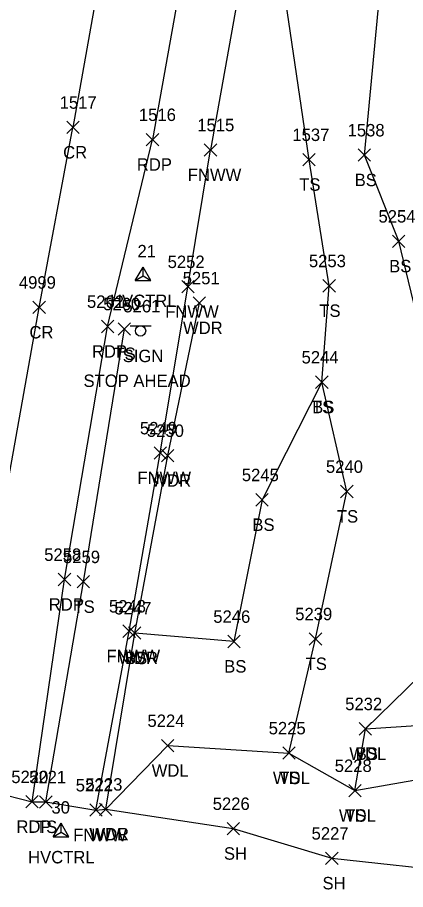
# Model space of a CAD drawing. Extents: x 1509053 to 1511576, y 400838 to 402572.
# Drawn here: x 1509729.1 to 1509791.5, y 401145.8 to 401286.1 of the extents above; entities that cross this region are included whole.
import ezdxf

# ---------------------------------------------------------------- set-up
doc = ezdxf.new("R2010")
doc.units = 0
for name, color, linetype in [('C_A', 7, 'Continuous'), ('C_I', 7, 'Continuous'), ('CPSM', 7, 'Continuous'), ('L_A', 7, 'Continuous'), ('L_I', 7, 'Continuous'), ('L_TIC', 7, 'Continuous'), ('LAWA', 7, 'Continuous'), ('LELB', 7, 'Continuous'), ('LFNC', 7, 'Continuous'), ('LSOGP', 7, 'Continuous'), ('P_A', 7, 'Continuous'), ('P_I', 7, 'Continuous'), ('P_TIC', 7, 'Continuous'), ('PET', 7, 'Continuous'), ('PRC', 7, 'Continuous'), ('S_A', 7, 'Continuous'), ('S_C', 7, 'Continuous'), ('S_I', 7, 'Continuous'), ('SSGN', 7, 'Continuous')]:
    doc.layers.add(name, color=color, linetype=linetype)

msp = doc.modelspace()

# ---------------------------------------------------------------- linework, layer by layer
at = {"layer": 'CPSM'}
for p, q in [((1509748.06, 401243.81), (1509749.31, 401245.97)), ((1509750.56, 401243.81), (1509749.31, 401245.97)), ((1509749.32, 401244.53), (1509749.31, 401245.97)), ((1509748.06, 401243.81), (1509749.32, 401244.53)), ((1509748.06, 401243.81), (1509750.56, 401243.81)), ((1509749.32, 401244.53), (1509749.32, 401244.53)), ((1509749.32, 401244.53), (1509750.56, 401243.81)), ((1509734.89, 401154.34), (1509736.14, 401156.51)), ((1509737.39, 401154.34), (1509736.14, 401156.51)), ((1509736.14, 401155.06), (1509736.14, 401156.51)), ((1509734.89, 401154.34), (1509736.14, 401155.06)), ((1509734.89, 401154.34), (1509737.39, 401154.34)), ((1509736.14, 401155.06), (1509736.14, 401155.06)), ((1509736.14, 401155.06), (1509737.39, 401154.34))]:
    msp.add_line(p, q, dxfattribs=at)
at = {"layer": 'L_TIC'}
for points in [[(1509759.17, 401263.81), (1509761.17, 401265.81)], [(1509761.17, 401263.81), (1509759.17, 401265.81)], [(1509783.91, 401262.98), (1509785.9, 401264.98)], [(1509785.9, 401262.98), (1509783.91, 401264.98)], [(1509775.02, 401262.24), (1509777.02, 401264.24)], [(1509777.02, 401262.24), (1509775.02, 401264.24)], [(1509789.44, 401249.12), (1509791.44, 401251.12)], [(1509791.44, 401249.12), (1509789.44, 401251.12)], [(1509755.53, 401241.81), (1509757.53, 401243.81)], [(1509757.53, 401241.81), (1509755.53, 401243.81)], [(1509778.25, 401241.95), (1509780.25, 401243.95)], [(1509780.25, 401241.95), (1509778.25, 401243.95)], [(1509757.38, 401239.19), (1509759.38, 401241.19)], [(1509759.38, 401239.19), (1509757.38, 401241.19)], [(1509745.31, 401235.02), (1509747.31, 401237.02)], [(1509747.31, 401235.02), (1509745.31, 401237.02)], [(1509777.07, 401226.46), (1509779.07, 401228.46)], [(1509779.07, 401226.46), (1509777.07, 401228.46)], [(1509777.07, 401226.46), (1509779.07, 401228.46)], [(1509779.07, 401226.46), (1509777.07, 401228.46)], [(1509751.08, 401215.06), (1509753.08, 401217.06)], [(1509753.08, 401215.06), (1509751.08, 401217.06)], [(1509752.29, 401214.65), (1509754.29, 401216.65)], [(1509754.29, 401214.65), (1509752.29, 401216.65)], [(1509781.08, 401208.87), (1509783.08, 401210.87)], [(1509783.08, 401208.87), (1509781.08, 401210.87)], [(1509767.46, 401207.53), (1509769.46, 401209.53)], [(1509769.46, 401207.53), (1509767.46, 401209.53)], [(1509738.72, 401194.35), (1509740.72, 401196.35)], [(1509740.72, 401194.35), (1509738.72, 401196.35)], [(1509746.09, 401186.41), (1509748.09, 401188.41)], [(1509748.09, 401186.41), (1509746.09, 401188.41)], [(1509746.97, 401186.1), (1509748.97, 401188.1)], [(1509748.97, 401186.1), (1509746.97, 401188.1)], [(1509746.97, 401186.1), (1509748.97, 401188.1)], [(1509748.97, 401186.1), (1509746.97, 401188.1)], [(1509762.93, 401184.75), (1509764.93, 401186.75)], [(1509764.93, 401184.75), (1509762.93, 401186.75)], [(1509776.05, 401185.16), (1509778.05, 401187.16)], [(1509778.05, 401185.16), (1509776.05, 401187.16)], [(1509784.08, 401170.7), (1509786.08, 401172.7)], [(1509786.08, 401170.7), (1509784.08, 401172.7)], [(1509784.08, 401170.7), (1509786.08, 401172.7)], [(1509786.08, 401170.7), (1509784.08, 401172.7)], [(1509752.29, 401168), (1509754.29, 401170)], [(1509754.29, 401168), (1509752.29, 401170)], [(1509771.78, 401166.81), (1509773.78, 401168.81)], [(1509773.78, 401166.81), (1509771.78, 401168.81)], [(1509771.78, 401166.81), (1509773.78, 401168.81)], [(1509773.78, 401166.81), (1509771.78, 401168.81)], [(1509782.4, 401160.76), (1509784.4, 401162.76)], [(1509784.4, 401160.76), (1509782.4, 401162.76)], [(1509782.4, 401160.76), (1509784.4, 401162.76)], [(1509784.4, 401160.76), (1509782.4, 401162.76)], [(1509732.69, 401158.94), (1509734.69, 401160.94)], [(1509734.69, 401158.94), (1509732.69, 401160.94)], [(1509740.75, 401157.63), (1509742.75, 401159.63)], [(1509742.75, 401157.63), (1509740.75, 401159.63)], [(1509742.31, 401157.76), (1509744.31, 401159.76)], [(1509744.31, 401157.76), (1509742.31, 401159.76)], [(1509742.31, 401157.76), (1509744.31, 401159.76)], [(1509744.31, 401157.76), (1509742.31, 401159.76)], [(1509762.83, 401154.65), (1509764.83, 401156.65)], [(1509764.83, 401154.65), (1509762.83, 401156.65)], [(1509778.68, 401149.88), (1509780.68, 401151.88)], [(1509780.68, 401149.88), (1509778.68, 401151.88)]]:
    msp.add_lwpolyline(points, dxfattribs=at)
at = {"layer": 'LAWA'}
for points in [[(1509743.31, 401158.76), (1509753.29, 401169), (1509772.78, 401167.81), (1509783.4, 401161.76), (1509785.08, 401171.7), (1509800.61, 401172.7), (1509812.47, 401171.07), (1509811.72, 401192.32), (1509812.58, 401209.09), (1509807.76, 401230.97), (1509813.05, 401256.02)], [(1509743.31, 401158.76), (1509747.97, 401187.1), (1509753.29, 401215.65), (1509758.38, 401240.19)]]:
    msp.add_lwpolyline(points, dxfattribs=at)
at = {"layer": 'LELB'}
for points in [[(1509784.91, 401263.98), (1509794.11, 401361.03)], [(1509776.02, 401263.24), (1509768.73, 401312.75)], [(1509779.25, 401242.95), (1509776.02, 401263.24)], [(1509790.44, 401250.12), (1509784.91, 401263.98)], [(1509785.08, 401171.7), (1509796.05, 401182.39), (1509797.2, 401198.58), (1509795.66, 401206.85), (1509794.77, 401232.19), (1509790.44, 401250.12)], [(1509772.78, 401167.81), (1509777.05, 401186.16), (1509782.08, 401209.87), (1509778.07, 401227.46), (1509779.25, 401242.95)], [(1509733.69, 401159.94), (1509739.72, 401195.35), (1509746.31, 401236.02)], [(1509778.07, 401227.46), (1509768.46, 401208.53), (1509763.93, 401185.75), (1509747.97, 401187.1)], [(1509783.4, 401161.76), (1509800.18, 401164.72), (1509810.11, 401160.61)]]:
    msp.add_lwpolyline(points, dxfattribs=at)
at = {"layer": 'LFNC'}
for points in [[(1509788.09, 401418.27), (1509778.14, 401361.9), (1509768.73, 401312.75), (1509760.17, 401264.81)], [(1509756.53, 401242.81), (1509760.17, 401264.81)], [(1509741.75, 401158.63), (1509747.09, 401187.41), (1509752.08, 401216.06), (1509756.53, 401242.81)]]:
    msp.add_lwpolyline(points, dxfattribs=at)
at = {"layer": 'LSOGP'}
msp.add_lwpolyline([(1509718.9, 401163.18), (1509731.47, 401159.97), (1509733.69, 401159.94), (1509741.75, 401158.63), (1509743.31, 401158.76), (1509763.83, 401155.65), (1509779.68, 401150.88), (1509801.41, 401148.54)], dxfattribs=at)
at = {"layer": 'P_TIC'}
for points in [[(1509737.04, 401267.43), (1509739.04, 401269.43)], [(1509739.04, 401267.43), (1509737.04, 401269.43)], [(1509749.83, 401265.46), (1509751.83, 401267.46)], [(1509751.83, 401265.46), (1509749.83, 401267.46)], [(1509731.62, 401238.49), (1509733.62, 401240.49)], [(1509733.62, 401238.49), (1509731.62, 401240.49)], [(1509742.61, 401235.4), (1509744.61, 401237.4)], [(1509744.61, 401235.4), (1509742.61, 401237.4)], [(1509735.68, 401194.71), (1509737.68, 401196.71)], [(1509737.68, 401194.71), (1509735.68, 401196.71)], [(1509730.47, 401158.97), (1509732.47, 401160.97)], [(1509732.47, 401158.97), (1509730.47, 401160.97)]]:
    msp.add_lwpolyline(points, dxfattribs=at)
at = {"layer": 'PET'}
for points in [[(1509812.34, 401557.62), (1509800.22, 401536.88), (1509792.46, 401505.8), (1509783.79, 401462.54), (1509775.66, 401414.3), (1509767.41, 401364.72), (1509759.54, 401315.03), (1509750.83, 401266.46)], [(1509743.61, 401236.4), (1509750.83, 401266.46)], [(1509731.47, 401159.97), (1509736.68, 401195.71), (1509743.61, 401236.4)]]:
    msp.add_lwpolyline(points, dxfattribs=at)
at = {"layer": 'PRC'}
for points in [[(1509754.64, 401366.79), (1509746.79, 401317.6), (1509738.04, 401268.43)], [(1509732.62, 401239.49), (1509738.04, 401268.43)], [(1509718.9, 401163.18), (1509725.18, 401197.96), (1509732.62, 401239.49)]]:
    msp.add_lwpolyline(points, dxfattribs=at)
at = {"layer": 'SSGN'}
for p, q in [((1509747.27, 401236.53), (1509750.6, 401236.53)), ((1509748.91, 401235.7), (1509748.91, 401235.7))]:
    msp.add_line(p, q, dxfattribs=at)
msp.add_circle((1509748.91, 401235.7), 0.833, dxfattribs=at)

# ---------------------------------------------------------------- texts
at = {"layer": 'C_A'}
for p in [(1509744.01, 401239.53), (1509730.83, 401150.06)]:
    msp.add_text('HVCTRL', height=2, dxfattribs=at).set_placement(p)
at = {"layer": 'C_I'}
for s, p in [('21', (1509748.42, 401247.53)), ('30', (1509734.59, 401158.06))]:
    msp.add_text(s, height=2, dxfattribs=at).set_placement(p)
at = {"layer": 'L_A'}
for s, p in [('FNWW', (1509756.51, 401259.81)), ('BS', (1509783.35, 401258.98)), ('TS', (1509774.43, 401258.24)), ('BS', (1509788.89, 401245.12)), ('FNWW', (1509752.88, 401237.81)), ('TS', (1509777.66, 401237.95)), ('WDR', (1509755.74, 401235.19)), ('TS', (1509744.72, 401231.02)), ('TS', (1509776.48, 401222.46)), ('BS', (1509776.51, 401222.46)), ('FNWW', (1509748.42, 401211.06)), ('WDR', (1509750.65, 401210.65)), ('TS', (1509780.49, 401204.87)), ('BS', (1509766.9, 401203.53)), ('TS', (1509738.13, 401190.35)), ('FNWW', (1509743.44, 401182.41)), ('WDR', (1509745.33, 401182.1)), ('BS', (1509746.41, 401182.1)), ('BS', (1509762.37, 401180.75)), ('TS', (1509775.46, 401181.16)), ('WDL', (1509782.5, 401166.7)), ('BS', (1509783.52, 401166.7)), ('WDL', (1509750.71, 401164)), ('WDL', (1509770.2, 401162.81)), ('TS', (1509771.19, 401162.81)), ('WDL', (1509780.82, 401156.76)), ('TS', (1509781.81, 401156.76)), ('TS', (1509732.1, 401154.94)), ('FNWW', (1509738.09, 401153.63)), ('WDR', (1509740.67, 401153.76)), ('WDL', (1509740.72, 401153.76)), ('SH', (1509762.32, 401150.65)), ('SH', (1509778.17, 401145.88))]:
    msp.add_text(s, height=2, dxfattribs=at).set_placement(p)
at = {"layer": 'L_I'}
for s, p in [('1515', (1509758.04, 401267.81)), ('1538', (1509782.21, 401266.98)), ('1537', (1509773.33, 401266.24)), ('5254', (1509787.18, 401253.12)), ('5252', (1509753.27, 401245.81)), ('5253', (1509775.99, 401245.95)), ('5251', (1509755.69, 401243.19)), ('5260', (1509742.91, 401239.02)), ('5244', (1509774.81, 401230.46)), ('5244', (1509774.81, 401230.46)), ('5249', (1509748.81, 401219.06)), ('5250', (1509749.94, 401218.65)), ('5240', (1509778.73, 401212.87)), ('5245', (1509765.2, 401211.53)), ('5259', (1509736.45, 401198.35)), ('5248', (1509743.83, 401190.41)), ('5247', (1509744.71, 401190.1)), ('5247', (1509744.71, 401190.1)), ('5246', (1509760.61, 401188.75)), ('5239', (1509773.79, 401189.16)), ('5232', (1509781.82, 401174.7)), ('5232', (1509781.82, 401174.7)), ('5224', (1509750.03, 401172)), ('5225', (1509769.52, 401170.81)), ('5225', (1509769.52, 401170.81)), ('5228', (1509780.14, 401164.76)), ('5228', (1509780.14, 401164.76)), ('5221', (1509731, 401162.94)), ('5222', (1509738.49, 401161.63)), ('5223', (1509740.05, 401161.76)), ('5223', (1509740.05, 401161.76)), ('5226', (1509760.52, 401158.65)), ('5227', (1509776.42, 401153.88))]:
    msp.add_text(s, height=2, dxfattribs=at).set_placement(p)
at = {"layer": 'P_A'}
for s, p in [('CR', (1509736.47, 401263.43)), ('RDP', (1509748.32, 401261.46)), ('CR', (1509731.05, 401234.49)), ('RDP', (1509741.1, 401231.4)), ('RDP', (1509734.16, 401190.71)), ('RDP', (1509728.96, 401154.97))]:
    msp.add_text(s, height=2, dxfattribs=at).set_placement(p)
at = {"layer": 'P_I'}
for s, p in [('1517', (1509735.91, 401271.43)), ('1516', (1509748.65, 401269.46)), ('4999', (1509729.35, 401242.49)), ('5262', (1509740.3, 401239.4)), ('5258', (1509733.42, 401198.71)), ('5220', (1509728.13, 401162.97))]:
    msp.add_text(s, height=2, dxfattribs=at).set_placement(p)
at = {"layer": 'S_A'}
msp.add_text('SIGN', height=2, dxfattribs=at).set_placement((1509746.05, 401230.68))
at = {"layer": 'S_C'}
msp.add_text('STOP AHEAD', height=2, dxfattribs=at).set_placement((1509739.74, 401226.68))
at = {"layer": 'S_I'}
msp.add_text('5261', height=2, dxfattribs=at).set_placement((1509746.15, 401238.68))

doc.saveas('drawing.dxf')
